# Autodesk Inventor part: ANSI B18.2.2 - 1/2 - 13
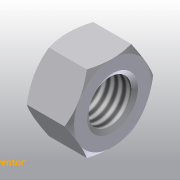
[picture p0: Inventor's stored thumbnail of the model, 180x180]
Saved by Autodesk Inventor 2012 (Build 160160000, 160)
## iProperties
Library Location: C:\Program Files\Local\Autodesk\Inventor 6\content
Library: local
SubLibrary: ANSI
Family: 1001
Member: 50
Member Major Revision: 1
Member Minor Revision: 1
Comments: To add or edit properties for Autodesk Inventor files, use iProperties.
Company: Autodesk
Created: 2002-10
Part Number: ANSI B18.2.2 - 1/2 - 13
Vendor: Autodesk Inc.
Document SubType Name: Modeling
Designer: Lieven Grauls
Description: Hex Nut
Standard: ANSI B18.2.2 1/2 - 13
Project: Valve Techcamp 2008
Density: 1 g/cm^3
Mass: 2.47828 g
Surface Area: 14.9858 cm^2
Volume: 2.47828 cm^3
Material: Default
Alert: To add or edit properties for Autodesk Inventor files, use iProperties.
Control State: 0
Master: False
Checked Out: False
Shininess: 64.0
Length Units: 11269
Angle Units: 11279
Time Units: 11290
Mass Units: 11283
Length Display Precision: 3
Angle Display Precision: 2
Compacted: True
EGR: 3
Classification: un/spsc 31161727
Density: 0.0
Volumn: 0.0
Area: 0.0
PropertySet Name: Model Information
Author: Lieven Grauls
Revision Number: 1
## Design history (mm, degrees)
sketch "Sketch1"
  geometry: L1 (-10.999, 0)-(-5.499, 9.525); L2 (-5.499, 9.525)-(5.499, 9.525); L3 (5.499, 9.525)-(10.999, 0); L4 (10.999, 0)-(5.499, -9.525); L5 (5.499, -9.525)-(-5.499, -9.525); L6 (-5.499, -9.525)-(-10.999, 0); 2 further points
  constraints: 12 end point, 1 coincident, 1 horizontal, 11 other
  dimensions: "d0" = 21.99705 distance of L3.end L1.start (= 1.1547 x SW)
extrude "Body" new body sketch "Sketch1" distance "d1" = 11.1252 (= KOH); taper "d2" = 0 deg
revolve "Chamfer1" stored, may be unused: angle "d7" = 90 deg
sketch "Sketch3"
  geometry: A1 r 9.525 centre (0, 0) between (-4.762, -8.249) and (4.763, -8.249) reference; 1 further point
  constraints: 1 coincident
hole "Thread" sketch "Sketch3" diameter "d25" = 10.5918; stored, may be unused: countersink angle "d29" = 82 deg, drill point angle "d31" = 118 deg; dims "d26" = 6, "d27" = 4, "d28" = 2, "d30" = 8
node "Volumenkörper1"
node "Volumenkörpern"
node "Oberflächenkörpern"
chamfer "Chamfer2" distance "d8" = 1.05755 (= -0.5 x GD1 + 0.5 x NND); stored, may be unused: angle "d9" = 30 deg, second distance "d40" = 1.05755 (= -0.5 x GD1 + 0.5 x NND)
chamfer "Chamfer3" distance "d10" = 1.05755 (= -0.5 x GD1 + 0.5 x NND); stored, may be unused: angle "d11" = 30 deg, second distance "d41" = 1.05755 (= -0.5 x GD1 + 0.5 x NND)
sketch "Sketch2"
  geometry: L1 (0, 5.499)-(0, 10.999) reference; L2 (0, 10.999)-(11.125, 10.999) reference; L3 (11.125, 5.499)-(11.125, 10.999) reference; L4 (-1.113, 0)-(14.463, 0) reference; L5 (0.851, 10.999)-(0, 9.525); L6 (10.274, 10.999)-(11.125, 9.525)
  constraints: 4 end point, 4 point on line
  dimensions: "d3" = 30 deg angle of L1 L5 (= ANG1); "d4" = 30 deg angle of L3 L6 (= ANG2); "d5" = 19.05 diameter of L5.end L4 (= SW0); "d6" = 19.05 diameter of L6.end L4 (= SW01)
other parameters: "ANG1" = 30 deg [user parameter; used in 1 equation term], "ANG2" = 30 deg [user parameter; used in 1 equation term], "NND" = 12.7 [user parameter; used in 4 equation terms], "KOH" = 11.1252 [user parameter; used in 1 equation term], "SW" = 19.05 [user parameter; used in 4 equation terms], "SW0" = 19.05 (= SW) [user parameter; used in 1 equation term], "SW01" = 19.05 (= SW) [user parameter; used in 1 equation term], "GD1" = 10.5849 (computed from THREADDIA, TPU, TOA) [user parameter; used in 4 equation terms], "d13" = 0, "d14" = 0, "d39" = 0, "TOA" = 30 deg [user parameter; used in 1 equation term], "PTC" = 1.95385 (computed from TPU) [user parameter], "THREADDIA" = 12.7 [user parameter; used in 1 equation term], "E0" = 22.00275 (= 1.155 x SW) [user parameter]
